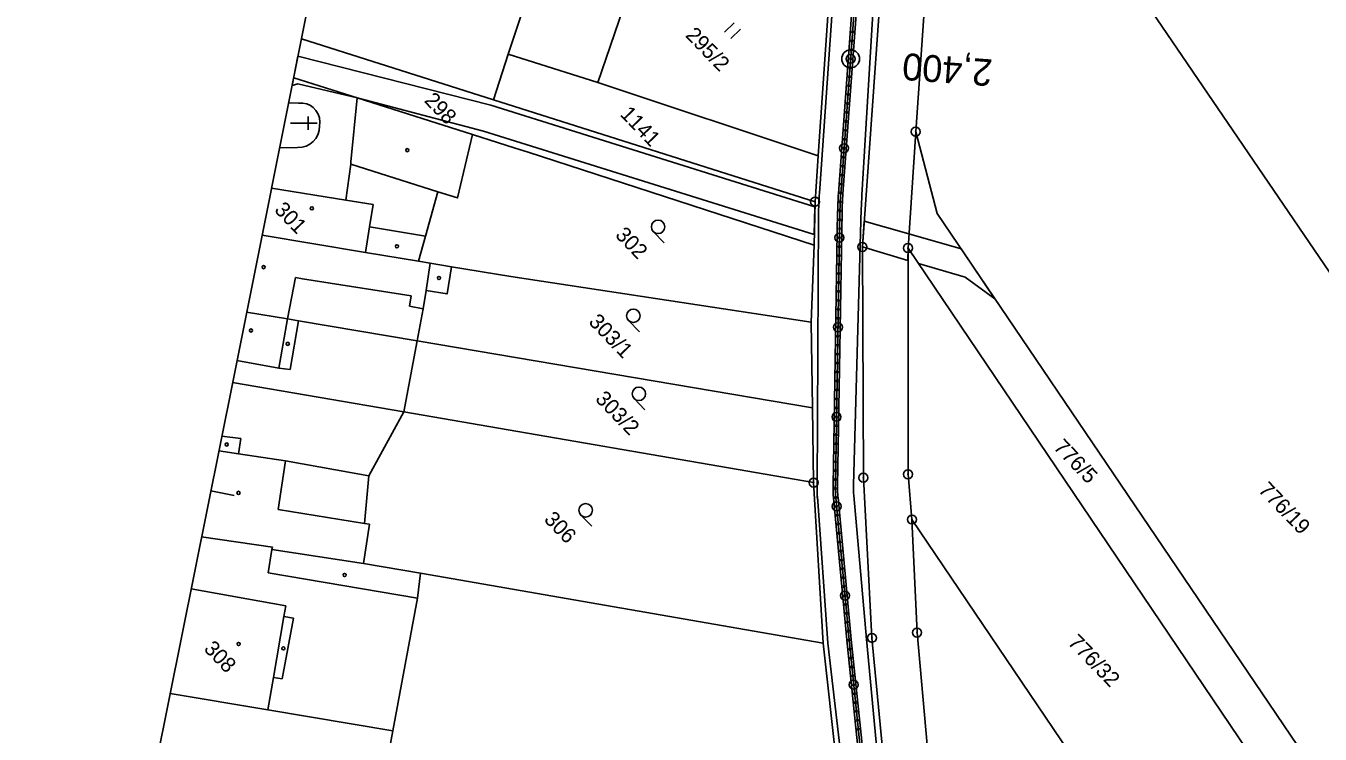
# Model space of a CAD drawing. Extents: x -548552 to -543113, y -1131925 to -1123599.
# Drawn here: x -547996.4 to -547852, y -1129312 to -1129232.9 of the extents above; entities that cross this region are included whole.
import ezdxf

# ---------------------------------------------------------------- set-up
doc = ezdxf.new("R2010")
doc.units = 0
for name, color, linetype in [('Hranice parcel', 7, 'Continuous'), ('Parcelní čísla', 7, 'Continuous'), ('Profile', 7, 'Continuous'), ('PROFILY NÁVRH', 7, 'Continuous'), ('STANIČENÍ', 7, 'Continuous'), ('Vnitřní kresba', 7, 'Continuous'), ('Věcná břemena k části', 7, 'Continuous'), ('Značky bodu BP', 7, 'Continuous'), ('Značky budov', 7, 'Continuous'), ('Značky kultur', 7, 'Continuous')]:
    doc.layers.add(name, color=color, linetype=linetype)

msp = doc.modelspace()

# ---------------------------------------------------------------- linework, layer by layer
at = {"layer": 'Hranice parcel'}
for p, q in [((-547893.76, -1129197.5), (-547897.12, -1129244.73)), ((-547893.76, -1129197.5), (-547826.6, -1129296.2)), ((-547937.55, -1129220.62), (-547942.59, -1129236.09)), ((-547927.38, -1129223.94), (-547932.61, -1129239.25)), ((-547908.01, -1129247.43), (-547906.88, -1129231.29)), ((-547965.66, -1129234.35), (-547944.24, -1129241.16)), ((-547944.24, -1129241.16), (-547942.59, -1129236.09)), ((-547942.59, -1129236.09), (-547932.61, -1129239.25)), ((-547966.53, -1129238.72), (-547959.45, -1129240.97)), ((-547932.61, -1129239.25), (-547908.01, -1129247.43)), ((-547946.58, -1129245.05), (-547959.45, -1129240.97)), ((-547908.35, -1129252.55), (-547944.24, -1129241.16)), ((-547897.12, -1129244.73), (-547897.98, -1129257.72)), ((-547894.72, -1129253.87), (-547897.12, -1129244.73)), ((-547908.35, -1129252.55), (-547908.01, -1129247.43)), ((-547908.47, -1129257.39), (-547908.35, -1129252.55)), ((-547908.77, -1129266.01), (-547908.47, -1129257.39)), ((-547897.98, -1129257.72), (-547836.99, -1129348.04)), ((-547967.22, -1129265.63), (-547966.01, -1129265.83)), ((-547952.08, -1129264.5), (-547952.75, -1129268.08)), ((-547966.01, -1129265.83), (-547952.75, -1129268.08)), ((-547908.64, -1129275.56), (-547908.77, -1129266.01)), ((-547952.75, -1129268.08), (-547954.23, -1129276)), ((-547952.75, -1129268.08), (-547908.64, -1129275.56)), ((-547908.52, -1129283.9), (-547908.64, -1129275.56)), ((-547954.23, -1129276), (-547908.52, -1129283.9)), ((-547907.46, -1129301.82), (-547908.52, -1129283.9)), ((-547897.54, -1129288.02), (-547841.57, -1129370.86)), ((-547897.54, -1129288.02), (-547896.97, -1129300.64)), ((-547958.74, -1129292.92), (-547952.39, -1129294.02)), ((-547952.39, -1129294.02), (-547907.46, -1129301.82)), ((-547896.97, -1129300.64), (-547894.74, -1129325.43)), ((-547903.92, -1129333.55), (-547907.46, -1129301.82))]:
    msp.add_line(p, q, dxfattribs=at)
for points in [[(-547821.33, -1128991.6), (-547858.78, -1129039.17), (-547867.17, -1129050.77), (-547872.99, -1129060.45), (-547877.72, -1129073.44), (-547883.99, -1129099.45), (-547892.72, -1129136.3), (-547895.31, -1129153.82), (-547897.09, -1129173.51), (-547903.07, -1129257.59), (-547902.96, -1129283.35), (-547902.01, -1129301.23), (-547897.46, -1129348.86), (-547895.9, -1129389.55), (-547894.79, -1129408.16)], [(-547959.45, -1129240.97), (-547960.14, -1129248.08), (-547960.17, -1129248.35), (-547960.7, -1129252.37), (-547969, -1129251.04)], [(-547967.09, -1129241.51), (-547965.99, -1129241.53)], [(-547965.99, -1129241.53), (-547965.53, -1129241.53), (-547965.07, -1129241.63), (-547964.65, -1129241.82), (-547964.37, -1129242.03), (-547964.05, -1129242.36), (-547963.81, -1129242.76), (-547963.66, -1129243.2), (-547963.61, -1129243.66), (-547963.65, -1129244.12), (-547963.69, -1129244.6), (-547963.83, -1129245.07), (-547964.06, -1129245.49), (-547964.34, -1129245.82), (-547964.71, -1129246.12), (-547965.14, -1129246.34), (-547965.6, -1129246.47), (-547966.09, -1129246.5)], [(-547952.6, -1129259.19), (-547951.83, -1129256.4), (-547950.45, -1129251.44), (-547948.25, -1129252.13), (-547946.58, -1129245.05)], [(-547908.47, -1129257.39), (-547940.38, -1129247.02), (-547941.82, -1129246.57), (-547946.58, -1129245.05)], [(-547966.09, -1129246.5), (-547968.1, -1129246.53)], [(-547835.61, -1129341.14), (-547894.72, -1129253.87)], [(-547970.05, -1129256.28), (-547958.51, -1129258.2), (-547952.6, -1129259.19)], [(-547897.98, -1129257.72), (-547897.98, -1129282.97), (-547897.54, -1129288.02)], [(-547952.6, -1129259.19), (-547951.3, -1129259.41), (-547948.93, -1129259.81)], [(-547948.93, -1129259.81), (-547949.41, -1129262.84), (-547951.76, -1129262.44), (-547952.08, -1129264.5)], [(-547948.93, -1129259.81), (-547942.3, -1129260.91), (-547908.77, -1129266.01)], [(-547971.78, -1129264.89), (-547967.22, -1129265.63)], [(-547973.35, -1129272.74), (-547954.23, -1129276)], [(-547958.74, -1129292.92), (-547958.08, -1129288.54), (-547958.62, -1129288.45), (-547958.15, -1129283.13), (-547954.23, -1129276)], [(-547976.8, -1129289.94), (-547968.91, -1129291.1), (-547968.96, -1129291.38), (-547958.74, -1129292.92)], [(-547952.39, -1129294.02), (-547952.73, -1129296.81), (-547955.47, -1129311.62), (-547956.48, -1129317.03)]]:
    msp.add_lwpolyline(points, dxfattribs=at)
at = {"layer": 'Profile'}
for p, q in [((-547950.2, -1129157.22), (-547973.3, -1129272.5)), ((-547950.2, -1129157.22), (-547973.3, -1129272.5)), ((-547973.3, -1129272.5), (-547996.41, -1129387.78)), ((-547973.3, -1129272.5), (-547996.41, -1129387.78)), ((-547973.3, -1129272.5), (-547996.41, -1129387.78)), ((-547973.19, -1129285.35), (-547975.78, -1129284.83))]:
    msp.add_line(p, q, dxfattribs=at)
at = {"layer": 'PROFILY NÁVRH'}
for p, q in [((-547905.65, -1129220.27), (-547907.87, -1129251.58)), ((-547905.74, -1129251.64), (-547903.39, -1129219.69)), ((-547905.24, -1129251.67), (-547902.89, -1129219.72)), ((-547901.22, -1129220.45), (-547903.12, -1129251.83)), ((-547907.97, -1129254.04), (-547908.12, -1129284.4)), ((-547906.34, -1129284.27), (-547905.83, -1129253.65)), ((-547905.84, -1129284.28), (-547905.33, -1129253.65)), ((-547903.2, -1129253.33), (-547904.05, -1129284.2)), ((-547908.09, -1129285.47), (-547906.93, -1129301.81)), ((-547904.81, -1129301.46), (-547906.29, -1129285.61)), ((-547904.31, -1129301.42), (-547905.79, -1129285.56)), ((-547904.02, -1129285.33), (-547902.63, -1129301.37)), ((-547901.75, -1129331), (-547904.81, -1129301.47)), ((-547901.25, -1129330.95), (-547904.31, -1129301.42)), ((-547902.63, -1129301.37), (-547899.78, -1129331.53)), ((-547903.6, -1129330.11), (-547906.93, -1129301.81))]:
    msp.add_line(p, q, dxfattribs=at)
for centre, major_axis, ratio, start_param, end_param in [((-547870.63, -1129254.23), (-2.97, -37.26), 0.998776, 4.720863, 4.786864), ((-547870.63, -1129254.23), (-2.8, -35.14), 0.998702, 4.718307, 4.775378), ((-547870.63, -1129254.23), (-2.76, -34.64), 0.998684, 4.718307, 4.775378), ((-547870.63, -1129254.23), (-2.59, -32.52), 0.998598, 4.718307, 4.764313), ((-547894.1, -1129284.47), (-2.6, -13.79), 0.999845, 4.882224, 4.991827), ((-547894.1, -1129284.47), (-2.27, -12.04), 0.999823, 4.882224, 4.991827), ((-547894.1, -1129284.47), (-2.18, -11.55), 0.999815, 4.882224, 4.991827), ((-547894.1, -1129284.47), (-1.85, -9.79), 0.999782, 4.871172, 4.984989)]:
    msp.add_ellipse(centre, major_axis=major_axis, ratio=ratio, start_param=start_param, end_param=end_param, dxfattribs=at)
at = {"layer": 'STANIČENÍ'}
for p, q in [((-547905.49, -1129251.66), (-547903.14, -1129219.71)), ((-547906.09, -1129284.27), (-547905.58, -1129253.65)), ((-547904.56, -1129301.44), (-547906.04, -1129285.59)), ((-547901.5, -1129330.97), (-547904.56, -1129301.44)), ((-547902.63, -1129301.37), (-547902.66, -1129301.03))]:
    msp.add_line(p, q, dxfattribs=at)
for centre, radius in [((-547904.16, -1129233.61), 0.1), ((-547904.24, -1129234.61), 0.1), ((-547904.38, -1129236.6), 1), ((-547904.38, -1129236.6), 0.5), ((-547904.38, -1129236.6), 0.1), ((-547904.31, -1129235.61), 0.1), ((-547904.46, -1129237.6), 0.1), ((-547904.6, -1129239.6), 0.1), ((-547904.53, -1129238.6), 0.1), ((-547904.68, -1129240.59), 0.1), ((-547904.82, -1129242.59), 0.1), ((-547904.75, -1129241.59), 0.1), ((-547904.9, -1129243.59), 0.1), ((-547904.97, -1129244.58), 0.1), ((-547905.12, -1129246.58), 0.5), ((-547905.12, -1129246.58), 0.1), ((-547905.04, -1129245.58), 0.1), ((-547905.19, -1129247.57), 0.1), ((-547905.34, -1129249.57), 0.1), ((-547905.27, -1129248.57), 0.1), ((-547905.41, -1129250.57), 0.1), ((-547905.55, -1129252.56), 0.1), ((-547905.49, -1129251.56), 0.1), ((-547905.58, -1129253.56), 0.1), ((-547905.61, -1129255.56), 0.1), ((-547905.6, -1129254.56), 0.1), ((-547905.63, -1129256.56), 0.5), ((-547905.63, -1129256.56), 0.1), ((-547905.65, -1129257.56), 0.1), ((-547905.68, -1129259.56), 0.1), ((-547905.66, -1129258.56), 0.1), ((-547905.7, -1129260.56), 0.1), ((-547905.73, -1129262.56), 0.1), ((-547905.71, -1129261.56), 0.1), ((-547905.75, -1129263.56), 0.1), ((-547905.78, -1129265.56), 0.1), ((-547905.76, -1129264.56), 0.1), ((-547905.8, -1129266.56), 0.5), ((-547905.8, -1129266.56), 0.1), ((-547905.83, -1129268.56), 0.1), ((-547905.81, -1129267.56), 0.1), ((-547905.85, -1129269.56), 0.1), ((-547905.86, -1129270.56), 0.1), ((-547905.9, -1129272.56), 0.1), ((-547905.88, -1129271.56), 0.1), ((-547905.91, -1129273.56), 0.1), ((-547905.95, -1129275.56), 0.1), ((-547905.93, -1129274.56), 0.1), ((-547905.96, -1129276.56), 0.5), ((-547905.96, -1129276.56), 0.1), ((-547906, -1129278.56), 0.1), ((-547905.98, -1129277.56), 0.1), ((-547906.01, -1129279.56), 0.1), ((-547906.05, -1129281.56), 0.1), ((-547906.03, -1129280.56), 0.1), ((-547906.06, -1129282.56), 0.1), ((-547906.08, -1129283.56), 0.1), ((-547906.09, -1129284.56), 0.1), ((-547906.04, -1129285.56), 0.1), ((-547905.95, -1129286.55), 0.5), ((-547905.95, -1129286.55), 0.1), ((-547905.86, -1129287.55), 0.1), ((-547905.77, -1129288.54), 0.1), ((-547905.67, -1129289.54), 0.1), ((-547905.58, -1129290.53), 0.1), ((-547905.49, -1129291.53), 0.1), ((-547905.39, -1129292.53), 0.1), ((-547905.3, -1129293.52), 0.1), ((-547905.21, -1129294.52), 0.1), ((-547905.12, -1129295.51), 0.1), ((-547905.02, -1129296.51), 0.5), ((-547905.02, -1129296.51), 0.1), ((-547904.93, -1129297.5), 0.1), ((-547904.84, -1129298.5), 0.1), ((-547904.74, -1129299.5), 0.1), ((-547904.65, -1129300.49), 0.1), ((-547904.56, -1129301.49), 0.1), ((-547904.46, -1129302.48), 0.1), ((-547904.35, -1129303.48), 0.1), ((-547904.25, -1129304.47), 0.1), ((-547904.04, -1129306.46), 0.5), ((-547904.15, -1129305.46), 0.1), ((-547904.04, -1129306.46), 0.1), ((-547903.94, -1129307.45), 0.1), ((-547903.84, -1129308.45), 0.1), ((-547903.73, -1129309.44), 0.1), ((-547903.63, -1129310.44), 0.1), ((-547903.53, -1129311.43), 0.1)]:
    msp.add_circle(centre, radius, dxfattribs=at)
for centre, major_axis, ratio, start_param, end_param in [((-547870.63, -1129254.23), (-2.78, -34.89), 0.998693, 4.718307, 4.775378), ((-547894.1, -1129284.47), (-2.22, -11.79), 0.999819, 4.882224, 4.991827)]:
    msp.add_ellipse(centre, major_axis=major_axis, ratio=ratio, start_param=start_param, end_param=end_param, dxfattribs=at)
at = {"layer": 'Vnitřní kresba'}
for p, q in [((-547960.17, -1129248.35), (-547950.45, -1129251.44)), ((-547960.7, -1129252.37), (-547957.66, -1129252.86)), ((-547957.66, -1129252.86), (-547958.06, -1129255.36)), ((-547958.06, -1129255.36), (-547958.51, -1129258.2)), ((-547958.06, -1129255.36), (-547951.83, -1129256.4)), ((-547951.3, -1129259.41), (-547951.76, -1129262.44)), ((-547967.22, -1129265.63), (-547966.34, -1129261.02)), ((-547966.34, -1129261.02), (-547965.54, -1129261.15)), ((-547965.54, -1129261.15), (-547953.42, -1129263.05)), ((-547953.42, -1129263.05), (-547953.61, -1129264.21)), ((-547953.61, -1129264.21), (-547952.08, -1129264.5)), ((-547968.17, -1129271.11), (-547967.22, -1129265.63)), ((-547966.94, -1129271.28), (-547966.01, -1129265.83)), ((-547972.86, -1129270.28), (-547968.17, -1129271.11)), ((-547968.17, -1129271.11), (-547966.94, -1129271.28)), ((-547974.55, -1129278.73), (-547972.43, -1129278.98)), ((-547972.43, -1129278.98), (-547972.67, -1129280.69)), ((-547974.88, -1129280.36), (-547972.67, -1129280.69)), ((-547972.67, -1129280.69), (-547967.45, -1129281.46)), ((-547967.45, -1129281.46), (-547968.26, -1129286.9)), ((-547967.45, -1129281.46), (-547958.15, -1129283.13)), ((-547968.26, -1129286.9), (-547958.62, -1129288.45)), ((-547968.96, -1129291.38), (-547969.37, -1129293.96)), ((-547969.37, -1129293.96), (-547952.73, -1129296.81)), ((-547977.97, -1129295.77), (-547967.4, -1129297.64)), ((-547967.62, -1129298.86), (-547968.8, -1129305.65)), ((-547967.4, -1129297.64), (-547967.62, -1129298.86)), ((-547967.62, -1129298.86), (-547966.55, -1129299.05)), ((-547966.55, -1129299.05), (-547967.81, -1129305.82)), ((-547968.8, -1129305.65), (-547969.43, -1129309.28)), ((-547967.81, -1129305.82), (-547968.8, -1129305.65)), ((-547969.43, -1129309.28), (-547980.31, -1129307.44)), ((-547955.47, -1129311.62), (-547969.43, -1129309.28))]:
    msp.add_line(p, q, dxfattribs=at)
at = {"layer": 'Věcná břemena k části'}
msp.add_line((-547966.05, -1129236.3), (-547966.7, -1129239.56), dxfattribs=at)
msp.add_lwpolyline([(-547966.7, -1129239.56), (-547966.07, -1129239.39), (-547959.45, -1129240.97), (-547945.36, -1129244.66), (-547908.44, -1129256.22), (-547908.37, -1129253.13), (-547944.53, -1129241.77), (-547966.05, -1129236.3)], dxfattribs=at)
msp.add_lwpolyline([(-547888.29, -1129263.37), (-547892.04, -1129257.82), (-547897.88, -1129256.14), (-547902.86, -1129254.71), (-547903.07, -1129257.59), (-547897.99, -1129259.1), (-547897.98, -1129257.72), (-547896.82, -1129259.44), (-547891.6, -1129260.98)], close=True, dxfattribs=at)
at = {"layer": 'Značky bodu BP'}
for centre, radius in [((-547897.12, -1129244.73), 0.5), ((-547897.12, -1129244.73), 0.0303), ((-547908.35, -1129252.55), 0.5), ((-547908.35, -1129252.55), 0.0303), ((-547903.07, -1129257.59), 0.5), ((-547903.07, -1129257.59), 0.0303), ((-547897.98, -1129257.72), 0.5), ((-547897.98, -1129257.72), 0.0303), ((-547902.96, -1129283.35), 0.5), ((-547897.98, -1129282.97), 0.5), ((-547897.98, -1129282.97), 0.0303), ((-547908.52, -1129283.9), 0.5), ((-547908.52, -1129283.9), 0.0303), ((-547902.96, -1129283.35), 0.0303), ((-547897.54, -1129288.02), 0.5), ((-547897.54, -1129288.02), 0.0303), ((-547896.97, -1129300.64), 0.5), ((-547902.01, -1129301.23), 0.5), ((-547902.01, -1129301.23), 0.0303), ((-547896.97, -1129300.64), 0.0303)]:
    msp.add_circle(centre, radius, dxfattribs=at)
at = {"layer": 'Značky budov'}
for p, q in [((-547963.9, -1129243.78), (-547966.9, -1129243.78)), ((-547964.9, -1129243.03), (-547964.9, -1129244.53))]:
    msp.add_line(p, q, dxfattribs=at)
for centre in [(-547953.85, -1129246.79), (-547964.51, -1129253.29), (-547955.01, -1129257.52), (-547969.88, -1129259.85), (-547950.32, -1129261.06), (-547971.3, -1129266.92), (-547967.19, -1129268.41), (-547974, -1129279.65), (-547972.69, -1129285.05), (-547960.85, -1129294.21), (-547972.67, -1129301.91), (-547967.68, -1129302.41)]:
    msp.add_circle(centre, 0.175, dxfattribs=at)
at = {"layer": 'Značky kultur'}
for p, q in [((-547918.45, -1129233.62), (-547917.37, -1129232.58)), ((-547917.75, -1129234.34), (-547916.67, -1129233.3)), ((-547926.41, -1129255.87), (-547925.2, -1129257.13)), ((-547929.17, -1129265.81), (-547927.96, -1129267.06)), ((-547928.55, -1129274.52), (-547927.34, -1129275.77)), ((-547934.49, -1129287.52), (-547933.27, -1129288.77))]:
    msp.add_line(p, q, dxfattribs=at)
for centre in [(-547925.87, -1129255.35), (-547928.63, -1129265.28), (-547928.01, -1129273.99), (-547933.95, -1129286.99)]:
    msp.add_circle(centre, 0.75, dxfattribs=at)

# ---------------------------------------------------------------- texts
at = {"layer": 'Parcelní čísla'}
for s, p in [('295/2', (-547922.91, -1129234.05)), ('298', (-547952.06, -1129241.33)), ('1141', (-547930.19, -1129242.87)), ('301', (-547968.78, -1129253.55)), ('302', (-547930.74, -1129256.35)), ('303/1', (-547933.71, -1129266.05)), ('303/2', (-547932.97, -1129274.65)), ('776/5', (-547881.84, -1129280.05)), ('776/19', (-547858.99, -1129284.82)), ('306', (-547938.69, -1129288.1)), ('308', (-547976.65, -1129302.54)), ('776/32', (-547880.23, -1129301.84))]:
    msp.add_text(s, height=1.7, rotation=313.9858, dxfattribs=at).set_placement(p)
at = {"layer": 'STANIČENÍ'}
msp.add_text('2,400', height=3, rotation=175.7829, dxfattribs=at).set_placement((-547888.48, -1129236.68))

doc.saveas('drawing.dxf')
